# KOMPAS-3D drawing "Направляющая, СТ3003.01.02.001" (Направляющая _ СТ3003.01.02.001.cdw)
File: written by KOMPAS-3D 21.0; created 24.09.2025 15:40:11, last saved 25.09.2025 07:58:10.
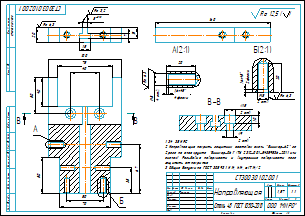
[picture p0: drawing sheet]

Sheet 1: A3, landscape

Document properties: Знак неуказанной шероховатости: 4; Параметр неуказанной шероховатости: Ra 12,5; Масса: 1.56864

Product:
- Part/product: Направляющая  | designation СТ3003.01.02.001
    Материал: Сталь 45  ГОСТ 1050-2013 (density 7810 kg/m3)
    Масса: 1.56864
    Форматы листов документа: A3

Title block, sheet 1: Наименование: Направляющая; designation: СТ3003.01.02.001; Материал: Сталь 45  ГОСТ 1050-2013; Масса: 1,57; Количество листов документа: 1; organisation: ООО "МИРО"; Форматы листов документа: A3; stored path: C:\Users\1\Yandex.Disk\Документы\Новая папка\Стапель №2\Стапель _ СТ3003.00.00.000\Опора _ СТ3003.01.00.000\2D\Кронштейн _ СТ3003.01.02.000\Направляющая _ СТ3003.01.02.001.cdw; Разработал: Тимонин

Views: Вид 1, Вид:1, Проекционный вид 2, Местный разрез 1, Проекционный вид 3, Разрез А-А, Выносной элемент 5, Выносной элемент 6, Разрез В-В, Выносной элемент А, Выносной элемент, Выносной элемент Б
Referenced files in C:\Users\1\Yandex.Disk\Документы\Новая папка\Стапель №2\Стапель _ СТ3003.00.00.000\Опора _ СТ3003.01.00.000\3D\Кронштейн _ СТ3003.01.02.000\: Направляющая _ СТ3003.01.02.001.m3d
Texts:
  Ra 3,2
  Ra 6,3
  Ra 12,5
  Ra 12,5 ( )
  СТ3003.01.02.000
  СТ3003.01.02.001 Направляющая
Dimensions and other numbers on the sheet: 8; 15; 7; 20; 75; 100; 50; 40; 35; 67; 70; 160; 10; 2 отв.; 9; 1,6; 4 фаски; 4 отв.; 2 фаски; 1:1; 1; 1,57

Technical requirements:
  34...38 HRC.
  Направляющию покрыть защитным составом эмаль "Виникор-62" за
  2 раза по слою грунта  "Виникор-061" (ТУ 2312-001-54359536-2011 или
  аналог). Резьбовые поверхности и внутренние поверхности паза
  защитить от покрытия.
  Общие допуски по ГОСТ 30893.1: Н14, h14, ± IT14/2.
